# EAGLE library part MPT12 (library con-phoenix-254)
PHOENIX CONNECTOR
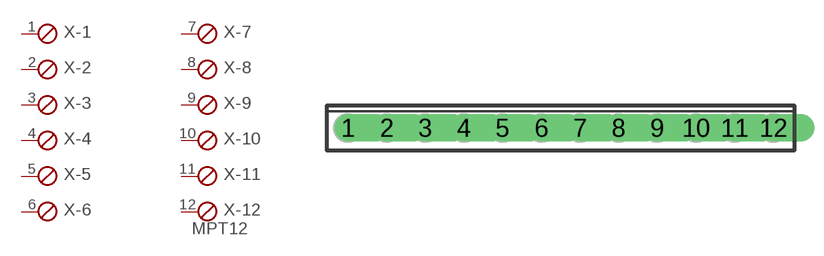
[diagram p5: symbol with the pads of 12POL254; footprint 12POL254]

Designator prefix X; gates -1=SKB -2=SKB -3=SKB -4=SKB -5=SKB -6=SKB -7=SKB -8=SKB -9=SKB -10=SKB -11=SKB -12=SKBV

## MPT12  [12POL254]
1  -1:1  pas
2  -2:1  pas
3  -3:1  pas
4  -4:1  pas
5  -5:1  pas
6  -6:1  pas
7  -7:1  pas
8  -8:1  pas
9  -9:1  pas
10  -10:1  pas
11  -11:1  pas
12  -12:1  pas

## Footprint 12POL254 (pad centres in mm)
PHOENIX CONNECTOR
drill 1.2 offset: 1 -13.97,0; 2 -11.43,0; 3 -8.89,0; 4 -6.35,0; 5 -3.81,0; 6 -1.27,0; 7 1.27,0; 8 3.81,0; 9 6.35,0; 10 8.89,0; 11 11.43,0; 12 13.97,0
